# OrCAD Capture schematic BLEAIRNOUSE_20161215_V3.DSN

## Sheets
1 Interface: size A
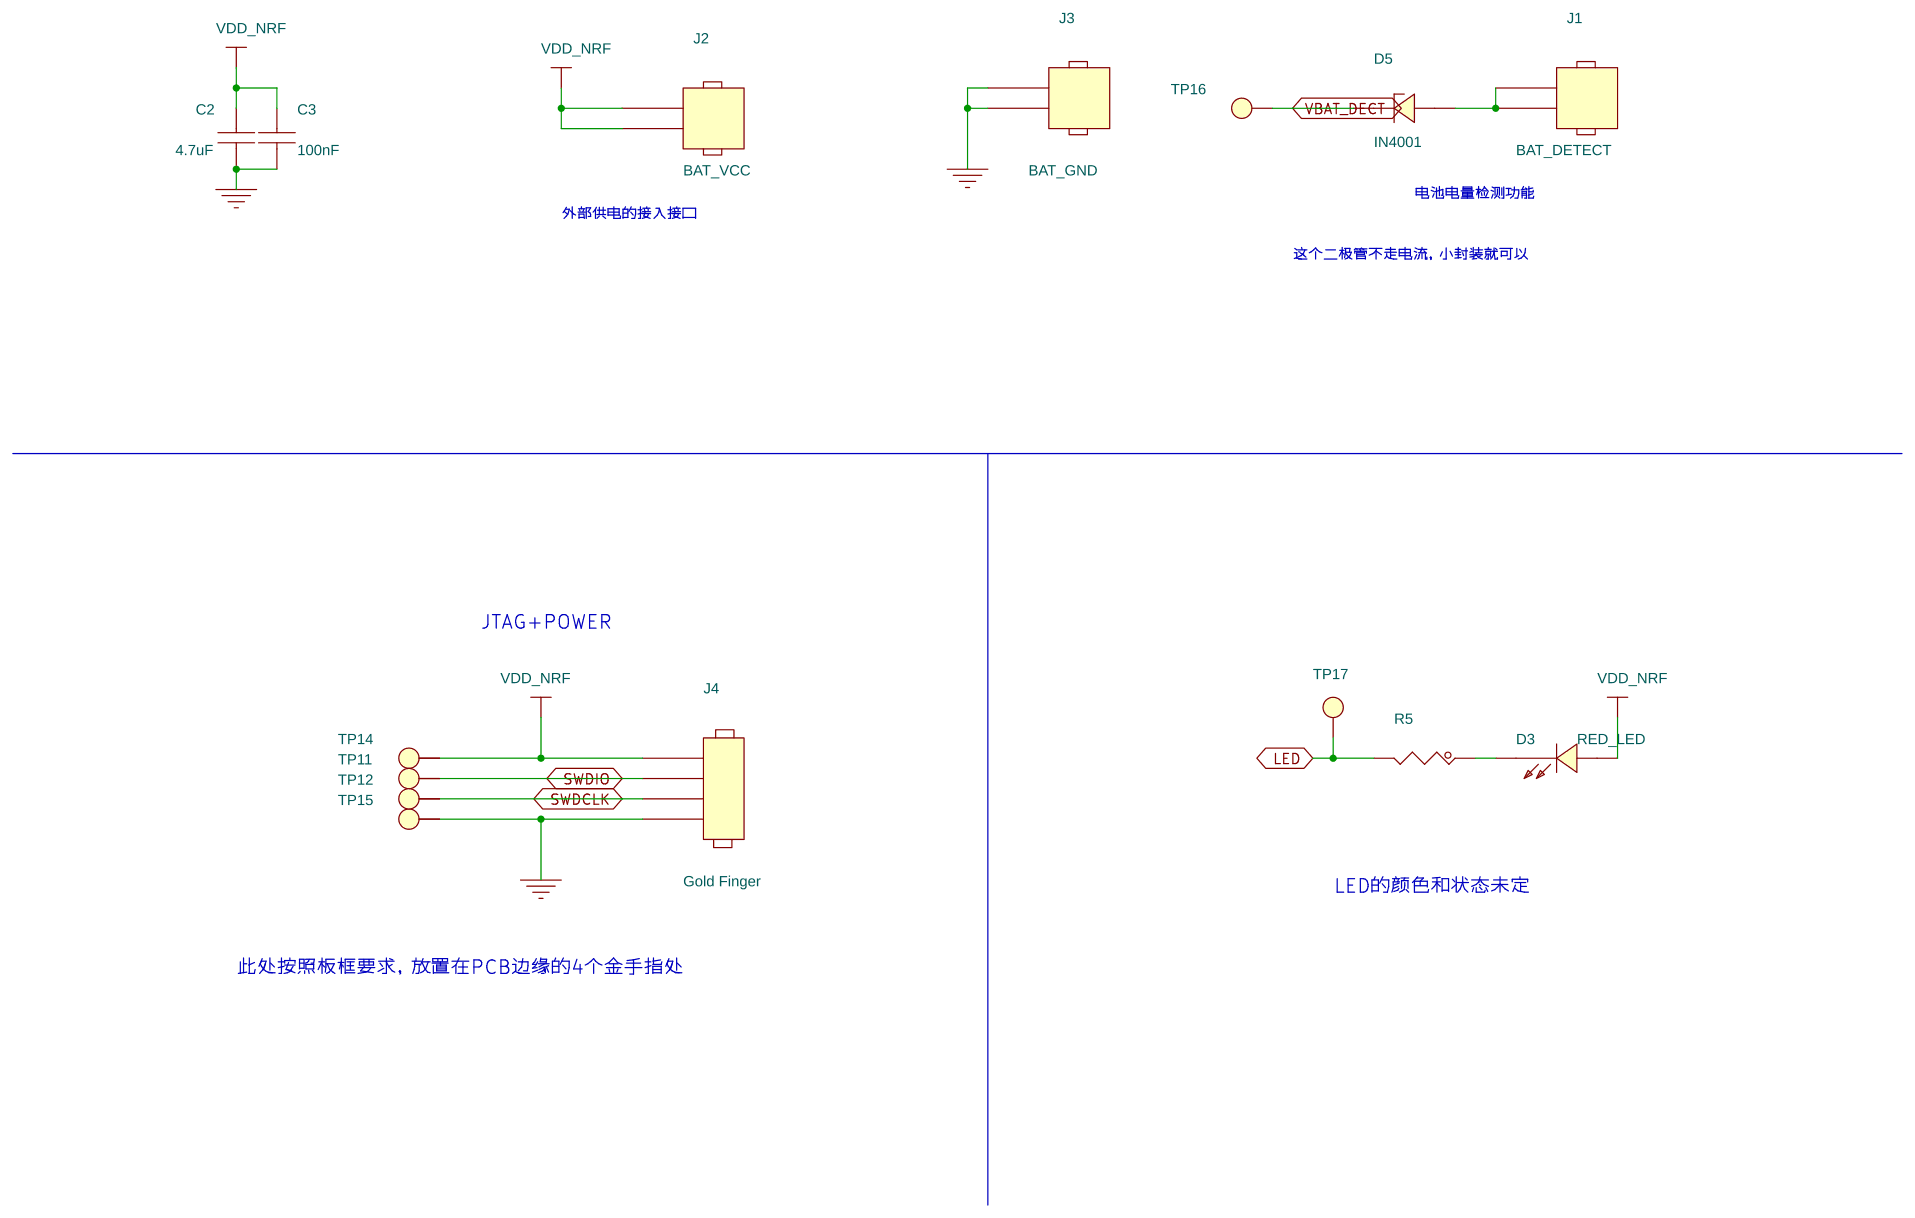
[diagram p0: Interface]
2 MISC: size A
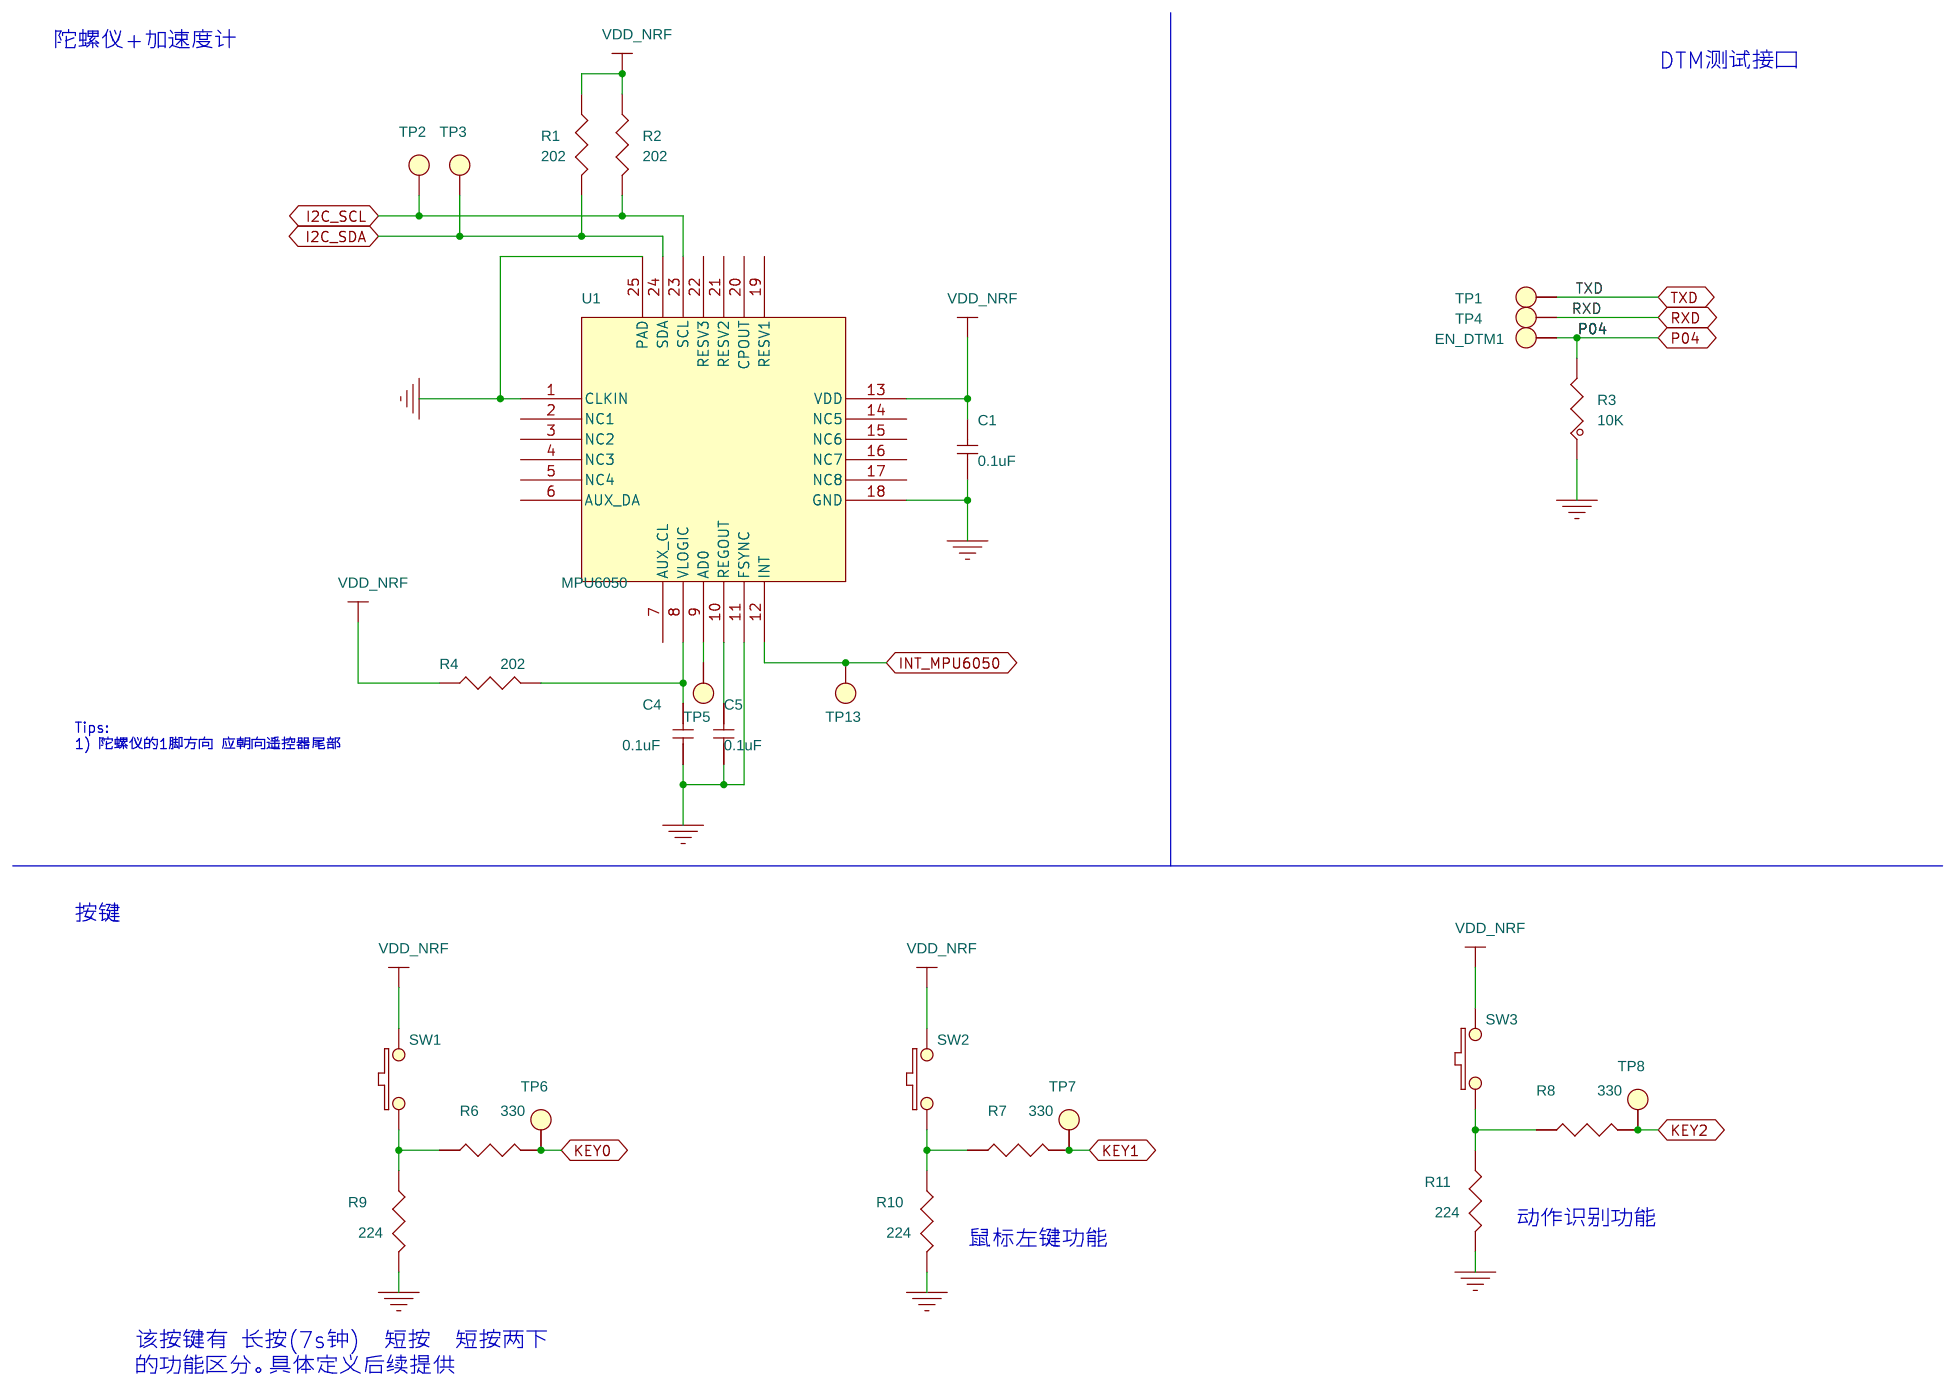
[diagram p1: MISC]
3 BLE_RF: size A
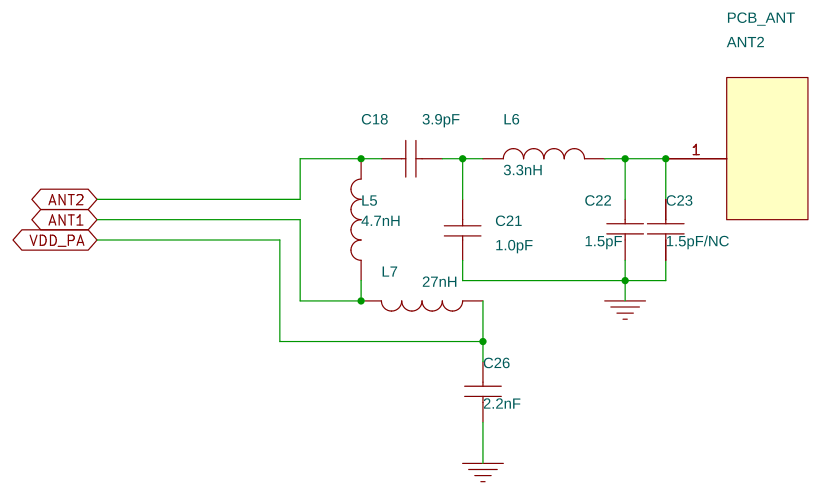
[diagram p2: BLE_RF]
4 nrf51822: size A
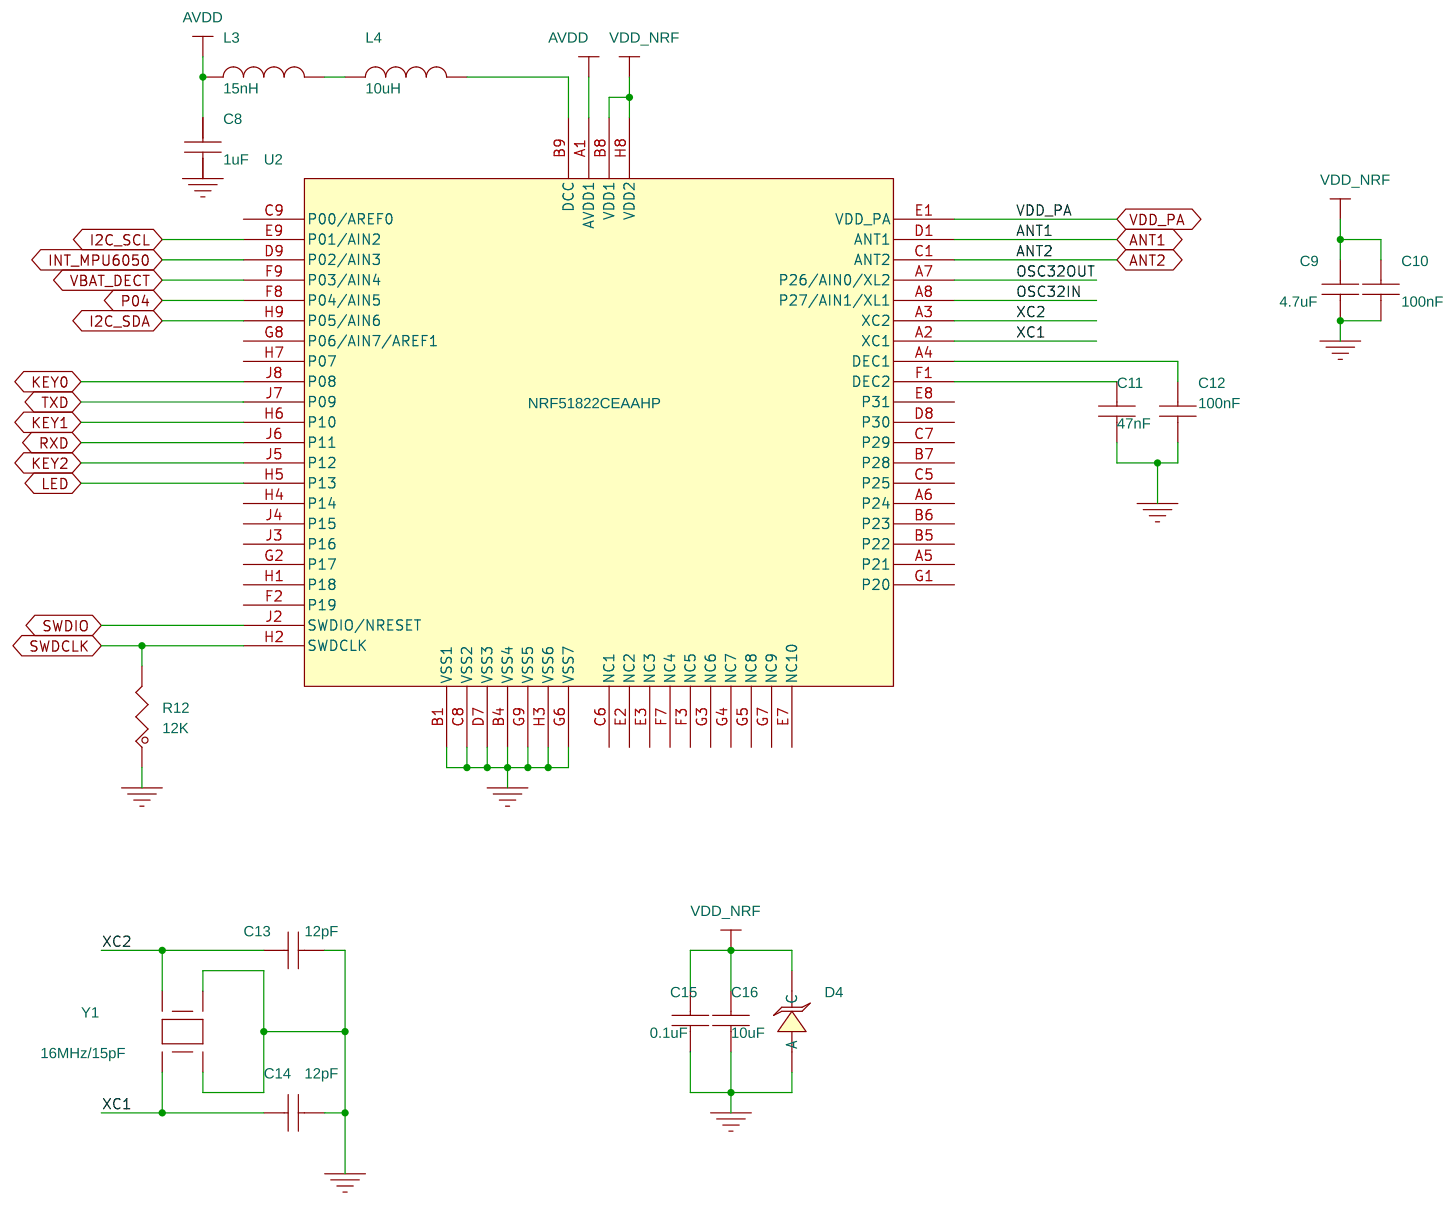
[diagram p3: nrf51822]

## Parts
sheet BLE_RF
ANT2  PCB_ANT  [ANT_PIFA_2G4_UPDATED_0MM6]
C18  3.9pF  [C0402]
C21  1.0pF  [C0402]
C22  1.5pF  [C0402]
C23  1.5pF/NC  [C0402]
C26  2.2nF  [C0402]
L5  4.7nH  [L0402]
L6  3.3nH  [L0402]
L7  27nH  [L0402]
sheet Interface
C2  4.7uF  [C0402]
C3  100nF  [C0402]
D3  RED_LED  [LED0603]
D5  IN4001  [SOD723]
J1  BAT_DETECT  [BAT-JC]
J2  BAT_VCC  [BAT+]
J3  BAT_GND  [BAT-]
J4  Gold Finger  [DIP4-2_0A]
R5  1k  [R0402]
TP11  TP_35MIL  [TP-1MM]
TP12  TP_35MIL  [TP-1MM]
TP14  TP_35MIL  [TP-1MM]
TP15  TP_35MIL  [TP-1MM]
TP16  TP_35MIL  [TP-1MM]
TP17  TP_35MIL  [TP-1MM]
sheet MISC
C1  0.1uF  [C0402]
C4  0.1uF  [C0402]
C5  0.1uF  [C0402]
EN_DTM1  TP_35MIL  [TP-1MM]
R1  202  [R0402]
R2  202  [R0402]
R3  10K  [R0402]
R4  202  [R0402]
R6  330  [R0402]
R7  330  [R0402]
R8  330  [R0402]
R9  224  [R0402]
R10  224  [R0402]
R11  224  [R0402]
SW1  SW PUSHBUTTON  [SW-3_5X2_7-SMD]
SW2  SW PUSHBUTTON  [SW-3_5X2_7-SMD]
SW3  SW PUSHBUTTON  [EVQP4]
TP1  TP_35MIL  [TP-1MM]
TP2  TP_35MIL  [TP-1MM]
TP3  TP_35MIL  [TP-1MM]
TP4  TP_35MIL  [TP-1MM]
TP5  TP_35MIL  [TP-1MM]
TP6  TP_35MIL  [TP-1MM]
TP7  TP_35MIL  [TP-1MM]
TP8  TP_35MIL  [TP-1MM]
TP13  TP_35MIL  [TP-1MM]
U1  MPU6050  [MPU-6880]
sheet nrf51822
C8  1uF  [C0402]
C9  4.7uF  [C0402]
C10  100nF  [C0402]
C11  47nF  [C0402]
C12  100nF  [C0402]
C13  12pF  [C0402]
C14  12pF  [C0402]
C15  0.1uF  [C0402]
C16  10uF  [C0402]
D4  ESD9L5.0ST5G  [SOD723]
L3  15nH  [L0402]
L4  10uH  [L0402]
R12  12K  [R0402]
U2  NRF51822CEAAHP  [NRF51822WLCSP]
Y1  16MHz/15pF  [X2520]

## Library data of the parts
ANT2 = Antenna_0: Descriptions: PCB ANTENNA, FOR 2.4GHz & 5GHz Band; MRVLPN: 6350050-00
C2 C3 C8-C16 C18 C21-C23 C26 = 10NF_0402_X7R_25V: Descriptions: CAP,X7R,0402,0.01uF,25V,10%; MRVLPN: 6310000-00; Part Number: GRM155R71E103KA01D; Part Type: CAP; Unit_Price($): 0.00065; Vendor: Murata; Vendor_P/N: GRM155R71E103KA01D; Datasheet: D:\Datasheet\MURATA\murata_cap.PDF
L3-L7 = L0402_2.7NH_ACX
D3 = LED
D5 = DIODE_BREAKDOWN_4
J1-J3 = HEADER_2
J4 = 4_HEADER
R5 = RES: RES MF 10.0K 1/16W 1% AEC-Q200 0402; AGILE_PN: 470-75416; CAD_APPROVED: Yes; FPLIST: RC0402_25,RC0402_HD,0402_CC; MFG_NAME01: KOA SPEER; MFG_PN01: RK73H1ETTP1002F; ROHS: Yes; SIGNAL_MODEL: DEFAULT_RESISTOR_10000OHM_2_1; Tolerance: 1%
EN_DTM1 TP1-TP8 TP11-TP17 = T_POINT_R: TEST POINT PAD .035 SMT, no part to order; AGILE_PN: 510-75618; CAD_APPROVED: Yes; HEIGHT: 0.1MM; ROHS: Yes
C1 C4 C5 = C
R1 R2 R4 R6-R11 = 240R_0402_1%: Descriptions: RES,THK,0402,240,1%,63mW; MRVLPN: 6360025-00; Part Number: RC0402FR-07240RL; Part Type: Resistor; Unit_Price($): 0.0004; Vendor: YAGEO; Vendor_P/N: RC0402FR-07240RL
R3 R12 = RES: Descriptions: RES,THK,0402,13.3K,1%,63mW; MRVLPN: 6360070-00; Part Number: RC0402FR-0713K3L; Part Type: Resistor; Vendor: YAGEO; Vendor_P/N: RC0402FR-0713K3L
SW1-SW3 = SW_PUSHBUTTON
U1 = MPU6050
D4 = DIODE_TVS_0: DIODE TVS ESD PROT ULT LOW CAP 5-5.4V SOD-923; AGILE_PN: 480-77934; CAD_APPROVED: Yes; HEIGHT: 0.40MM; MFG_NAME01: ON SEMICONDUCTOR; ROHS: Yes
U2 = NRF51822CEAAHP
Y1 = CRYSTAL_DIP_0: Descriptions: TXC,DIP HC-49S 9B SERIES,12MHz/18pF,30PPM,Fundamental; MRVLPN: 6350020-00; Part Number: 12MHz/18pF; Vendor: TXC; Vendor_P/N: 12MHz_18pF

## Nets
AVDD: C8.1 L3.2 U2.A1(AVDD1)
GND: C1.2 C2.2 C3.2 C4.2 C5.2 C8.2 C9.2 C10.2 C11.2 C12.2 C13.2 C14.2 C15.2 C16.2 C21.1 C22.2 C23.2 C26.2 D4.1(A) J3.1 J3.2 J4.1 R3.1 R9.2 R10.2 R11.2 R12.1 TP15.1(TP) U1.1(CLKIN) U1.11(FSYNC) U1.18(GND) U1.25(PAD) U2.B1(VSS1) U2.B4(VSS4) U2.C8(VSS2) U2.D7(VSS3) U2.G6(VSS7) U2.G9(VSS5) U2.H3(VSS6) Y1.2 Y1.4
VBAT_DECT: D5.2(CATHODE) TP16.1(TP) U2.F9(P03/AIN4)
VDD_nRF: C1.1 C2.1 C3.1 C9.1 C10.1 C15.1 C16.1 D3.1(ANODE) D4.2(C) J2.1 J2.2 J4.4 R1.1 R2.1 R4.1 SW1.2 SW2.2 SW3.2 TP14.1(TP) U1.13(VDD) U2.B8(VDD1) U2.H8(VDD2)
VDD_PA: C26.1 L7.1 U2.E1(VDD_PA)
ANT1: L5.1 L7.2 U2.D1(ANT1)
ANT2: C18.1 L5.2 U2.C1(ANT2)
I2C_SCL: R2.2 TP2.1(TP) U1.23(SCL) U2.E9(P01/AIN2)
I2C_SDA: R1.2 TP3.1(TP) U1.24(SDA) U2.H9(P05/AIN6)
INT_MPU6050: TP13.1(TP) U1.12(INT) U2.D9(P02/AIN3)
KEY0: R6.2 TP6.1(TP) U2.J8(P08)
KEY1: R7.2 TP7.1(TP) U2.H6(P10)
KEY2: R8.2 TP8.1(TP) U2.J5(P12)
LED: R5.2 TP17.1(TP) U2.H5(P13)
OSC32IN: U2.A8(P27/AIN1/XL1)
OSC32OUT: U2.A7(P26/AIN0/XL2)
P04: EN_DTM1.1(TP) R3.2 U2.F8(P04/AIN5)
RXD: TP4.1(TP) U2.J6(P11)
SWDCLK: J4.2 R12.2 TP12.1(TP) U2.H2(SWDCLK)
SWDIO: J4.3 TP11.1(TP) U2.J2(SWDIO/NRESET)
TXD: TP1.1(TP) U2.J7(P09)
XC1: C14.1 U2.A2(XC1) Y1.3(sig2)
XC2: C13.1 U2.A3(XC2) Y1.1(sig1)
N756550: C4.1 R4.2 U1.8(VLOGIC)
N756642: C5.1 U1.10(REGOUT)
N760581: R6.1 R9.1 SW1.1
N760880: R7.1 R10.1 SW2.1
N761183: R8.1 R11.1 SW3.1
N770152: TP5.1(TP) U1.9(AD0)
N772398: C11.1 U2.F1(DEC2)
N772402: C12.1 U2.A4(DEC1)
N774070: L3.1 L4.2
N774429: L4.1 U2.B9(DCC)
N780506: D5.1 J1.1 J1.2
N781791: D3.2(CATHODE) R5.1
N786255: ANT2.1 C22.1 C23.1 L6.1
N786271: C18.2 C21.2 L6.2

Not connected (* = marked no-connect by the designer): U1 2(NC1) 3(NC2) 4(NC3) 5(NC4) 6(AUX_DA) 7(AUX_CL) 14(NC5) 15(NC6) 16(NC7) 17(NC8) 19(RESV1) 20(CPOUT) 21(RESV2) 22(RESV3); U2 A5(P21) A6(P24) B5(P22) B6(P23) B7(P28) C5(P25) C6(NC1) C7(P29) C9(P00/AREF0) D8(P30) E2(NC2) E3(NC3) E7(NC10) E8(P31) F2(P19) F3(NC5) F7(NC4) G1(P20) G2(P17) G3(NC6) G4(NC7) G5(NC8) G7(NC9) G8(P06/AIN7/AREF1) H1(P18) H4(P14) H7(P07) J3(P16) J4(P15)

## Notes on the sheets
sheet 1
- 电池电量检测功能
- 外部供电的接入接口
- 这个二极管不走电流，小封装就可以
- JTAG+POWER
- LED的颜色和状态未定
- 此处按照板框要求，放置在PCB边缘的4个金手指处
sheet 2
- 陀螺仪+加速度计
- DTM测试接口
- Tips:
  1) 陀螺仪的1脚方向 应朝向遥控器尾部
- 按键
- 动作识别功能
- 鼠标左键功能
- 该按键有 长按(7s钟)  短按  短按两下
  的功能区分。具体定义后续提供
